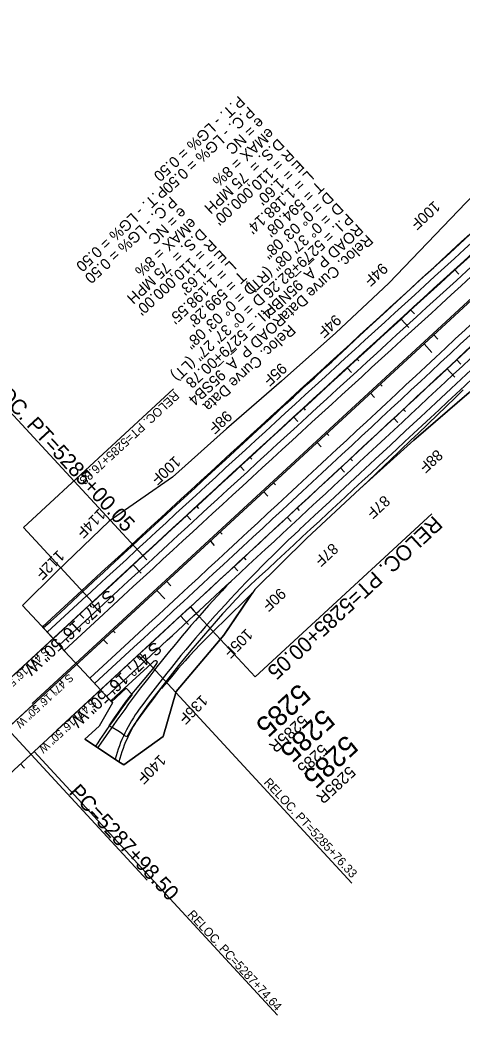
# Model space of a CAD drawing. Extents: x 2160876 to 2175990, y 601436 to 618246.
# Drawn here: x 2163718 to 2164326, y 605458 to 606830 of the extents above; entities that cross this region are included whole.
import ezdxf

# ---------------------------------------------------------------- set-up
doc = ezdxf.new("R2010")
doc.units = 0
for name, color, linetype in [('BNDY-ADJ', 7, 'Continuous'), ('BNDY-ADJ-TXT', 7, 'Continuous'), ('EX-UTIL-ELEC-TXT', 7, 'Continuous'), ('RD_DTM_Major2', 7, 'Continuous'), ('RD_EX_BldgApp_Sign', 7, 'Continuous'), ('RD_EX_BldgApp_Steps', 7, 'Continuous'), ('RD_EX_DV_TX_Prop', 7, 'Continuous'), ('RD_EX_Fence_Gate', 7, 'Continuous'), ('RD_EX_Parking_Conc', 7, 'Continuous'), ('RD_EX_RW', 7, 'Continuous'), ('RD_HC_Cl', 7, 'Continuous'), ('RD_HC_Data_Tic', 7, 'Continuous'), ('RD_HC_TX_Sta50', 7, 'Continuous'), ('RD_TX_RoadID', 7, 'Continuous')]:
    doc.layers.add(name, color=color, linetype=linetype)

msp = doc.modelspace()

# ---------------------------------------------------------------- linework, layer by layer
at = {"layer": 'BNDY-ADJ'}
msp.add_line((2172239.9, 613739.9), (2163704.8, 605858.6), dxfattribs=at)
at = {"layer": 'BNDY-ADJ-TXT'}
for p, q in [((2163817.9, 606028.4), (2163672.2, 605893.8)), ((2163883.1, 605957.8), (2163737.4, 605823.3))]:
    msp.add_line(p, q, dxfattribs=at)
for centre, radius, start, end in [((2238443, 525213.1), 110000, 132.100607, 132.719474), ((2089258, 686773.1), 110000, 312.719474, 313.338341), ((2169535, 599544.7), 8545.9, 132.71947, 164.41949)]:
    msp.add_arc(centre, radius, start, end, dxfattribs=at)
at = {"layer": 'EX-UTIL-ELEC-TXT'}
for p, q in [((2163809.8, 606037.2), (2163755.7, 605987.2)), ((2163817.9, 606028.4), (2163763.8, 605978.4)), ((2163826.1, 606019.5), (2163772, 605969.6)), ((2163874.9, 605966.6), (2163820.8, 605916.7)), ((2163883.1, 605957.8), (2163828.9, 605907.9)), ((2163891.2, 605949), (2163837.1, 605899))]:
    msp.add_line(p, q, dxfattribs=at)
for centre, radius, start, end in [((2238443, 525213.1), 110012, 132.100607, 132.719474), ((2238443, 525213.1), 110000, 132.100607, 132.719474), ((2238443, 525213.1), 109988, 132.100607, 132.719474), ((2089258, 686773.1), 109988, 312.719474, 313.338341), ((2089258, 686773.1), 110000, 312.719474, 313.338341), ((2089258, 686773.1), 110012, 312.802799, 313.338341), ((2089258, 686773.1), 110024, 312.863734, 313.338341), ((2165306.8, 604831), 1770, 132.8638, 143.5951), ((2165306.8, 604831), 1786, 136.6199, 146.0495), ((2089258, 686773.1), 110012, 312.719474, 312.802799), ((2164048.7, 605758.6), 206.9, 143.5951, 164.8838)]:
    msp.add_arc(centre, radius, start, end, dxfattribs=at)
at = {"layer": 'RD_DTM_Major2'}
for p, q in [((2164273.9, 606384), (2164284.7, 606372.3)), ((2164200.4, 606316.2), (2164205.8, 606310.3)), ((2164126.9, 606248.3), (2164132.3, 606242.5)), ((2164053.5, 606180.5), (2164058.9, 606174.6)), ((2163980, 606112.7), (2163985.4, 606106.8)), ((2163906.5, 606044.8), (2163917.4, 606033.1)), ((2163833, 605977), (2163838.5, 605971.1)), ((2163759.6, 605909.1), (2163765, 605903.3))]:
    msp.add_line(p, q, dxfattribs=at)
at = {"layer": 'RD_EX_BldgApp_Sign'}
msp.add_line((2165000.3, 607057.6), (2163734.9, 605889.1), dxfattribs=at)
at = {"layer": 'RD_EX_BldgApp_Steps'}
for p, q in [((2172672.7, 614139.6), (2163700.6, 605854.7)), ((2164255.4, 606431), (2164260.8, 606425.1)), ((2164287.3, 606396.4), (2164292.7, 606390.5)), ((2164181.6, 606363.5), (2164184.3, 606360.5)), ((2164319, 606362.1), (2164324.5, 606356.2)), ((2163648.5, 606351.1), (2163887.2, 606092.6)), ((2164213.8, 606328.6), (2164216.5, 606325.6)), ((2164107.9, 606295.9), (2164110.6, 606292.9)), ((2164245.8, 606293.9), (2164248.6, 606291)), ((2164140.3, 606260.7), (2164143, 606257.8)), ((2164034.3, 606228.2), (2164037, 606225.3)), ((2164172.6, 606225.9), (2164175.3, 606222.9)), ((2164066.9, 606192.9), (2164069.6, 606189.9)), ((2163960.7, 606160.5), (2163963.5, 606157.5)), ((2164099.3, 606157.9), (2164102, 606154.9)), ((2164284.6, 606150.3), (2164041.4, 605925.7)), ((2163993.4, 606125), (2163996.1, 606122.1)), ((2163887.2, 606092.6), (2163703.5, 605923)), ((2163887.2, 606092.7), (2163892.7, 606086.8)), ((2164025.9, 606089.9), (2164028.6, 606087)), ((2163919.9, 606057.2), (2163925.4, 606051.3)), ((2163952.4, 606022), (2163768.7, 605852.4)), ((2163813.8, 606024.8), (2163816.5, 606021.9)), ((2164041.4, 605925.7), (2163952.4, 606022)), ((2163952.5, 606022), (2163957.9, 606016.2)), ((2163846.5, 605989.4), (2163849.2, 605986.4)), ((2163740.3, 605957), (2163743, 605954)), ((2163879, 605954.2), (2163881.7, 605951.3)), ((2163773, 605921.5), (2163775.7, 605918.6)), ((2163735.2, 605886.6), (2163737.9, 605883.6)), ((2163805.5, 605886.4), (2163808.2, 605883.4)), ((2163700.6, 605854.7), (2163893, 605646.3))]:
    msp.add_line(p, q, dxfattribs=at)
for centre, start, end in [((2238512.2, 525277.4), 132.095186, 132.719474), ((2089327.4, 686837.3), 312.719474, 313.335811)]:
    msp.add_arc(centre, 110000, start, end, dxfattribs=at)
at = {"layer": 'RD_EX_Fence_Gate'}
for p, q in [((2164225.6, 606467.6), (2164152.6, 606399.2)), ((2164152.6, 606399.2), (2164077.9, 606332.8)), ((2164077.9, 606332.8), (2164002.4, 606267.1)), ((2164002.4, 606267.1), (2163927.7, 606200.7)), ((2163927.7, 606200.7), (2163841, 606140.1)), ((2163841, 606140.1), (2163768.7, 606071)), ((2163768.7, 606071), (2163721.5, 606024.2)), ((2163747.5, 605996), (2163721.5, 606024.2)), ((2163998.3, 605983.1), (2163932.8, 605905.8)), ((2163780, 605960.8), (2163812.7, 605925.5)), ((2163932.8, 605905.8), (2163915, 605844)), ((2163845.2, 605890.2), (2163826.8, 605858)), ((2163826.8, 605858), (2163807.5, 605840.2)), ((2163821.9, 605830.6), (2163807.5, 605840.2)), ((2163915, 605844), (2163860.8, 605804.7)), ((2163860.8, 605804.7), (2163854.2, 605809.1))]:
    msp.add_line(p, q, dxfattribs=at)
for points in [[(2164225.6, 606467.6), (2164332.1, 606578.3), (2164419, 606668.6), (2164457.4, 606753.8), (2164511.4, 606873.3), (2164543.9, 606914.3), (2164546.6, 606930.7)], [(2164878.1, 606761.5), (2164843.2, 606725.6), (2164806, 606692.2), (2164768.4, 606659.1), (2164729.9, 606627.2), (2164693.8, 606592.6), (2164655.6, 606560.2), (2164612.2, 606533.5), (2164562.8, 606513.4), (2164521, 606484.9), (2164446.2, 606418.5), (2164410.1, 606383.9), (2164335.8, 606317), (2164259.9, 606251.7), (2164185.8, 606184.6), (2164112.5, 606116.5), (2164041.3, 606046.2), (2163998.3, 605983.1)]]:
    msp.add_lwpolyline(points, dxfattribs=at)
at = {"layer": 'RD_EX_RW'}
for p, q in [((2164225.6, 606467.6), (2164152.6, 606399.2)), ((2164152.6, 606399.2), (2164077.9, 606332.8)), ((2164077.9, 606332.8), (2164002.4, 606267.1)), ((2164002.4, 606267.1), (2163927.7, 606200.7)), ((2163927.7, 606200.7), (2163841, 606140.1)), ((2163841, 606140.1), (2163768.7, 606071)), ((2163768.7, 606071), (2163721.5, 606024.2)), ((2163998.3, 605983.1), (2164037.6, 606040.8)), ((2164037.6, 606040.8), (2164031.7, 606035.1)), ((2163721.5, 606024.2), (2163747.5, 605996)), ((2163747.5, 605996), (2163780, 605960.8)), ((2163747.5, 605996), (2163750.2, 605993.1)), ((2163932.8, 605905.8), (2163998.3, 605983.1)), ((2163845.2, 605890.2), (2163812.7, 605925.5)), ((2163915, 605844), (2163932.8, 605905.8)), ((2163845.2, 605890.2), (2163826.8, 605858)), ((2163842.9, 605892.7), (2163845.2, 605890.2)), ((2163826.8, 605858), (2163807.5, 605840.2)), ((2163807.5, 605840.2), (2163821.9, 605830.6)), ((2163860.8, 605804.7), (2163915, 605844)), ((2163854.2, 605809.1), (2163821.9, 605830.6)), ((2163821.9, 605830.6), (2163854.2, 605809.1)), ((2163854.2, 605809.1), (2163860.8, 605804.7))]:
    msp.add_line(p, q, dxfattribs=at)
for points in [[(2164546.4, 606929.7), (2164543.9, 606914.3), (2164511.4, 606873.3), (2164457.4, 606753.8), (2164419, 606668.6), (2164332.1, 606578.3), (2164225.6, 606467.6)], [(2164185.8, 606184.6), (2164259.9, 606251.7), (2164335.8, 606317), (2164410.1, 606383.9), (2164446.2, 606418.5), (2164521, 606484.9), (2164562.8, 606513.4), (2164612.2, 606533.5), (2164655.6, 606560.2), (2164693.8, 606592.6), (2164729.9, 606627.2), (2164768.4, 606659.1), (2164806, 606692.2), (2164843.2, 606725.6), (2164878.1, 606761.5)], [(2163750.2, 605993.1), (2163759.9, 606002), (2163768.1, 606009.5), (2163780.5, 606020.9), (2163790.2, 606030.1), (2163798.6, 606037.9), (2163810.3, 606048.6), (2163819.8, 606057.4), (2163832.5, 606069.2), (2163841.4, 606077.4), (2163848.1, 606083.6), (2163861.4, 606096), (2163871, 606104.7), (2163882.2, 606115.1), (2163891.7, 606123.8), (2163909.2, 606140.1), (2163919.9, 606150), (2163938.8, 606167.4), (2163958.4, 606185.6), (2163969.7, 606196), (2163987, 606212.1), (2164000.8, 606224.6), (2164020.1, 606242.4), (2164031.4, 606252.9), (2164050.9, 606270.9), (2164063.1, 606282), (2164083, 606300.4), (2164094.4, 606310.8), (2164105.1, 606320.7), (2164112.9, 606328), (2164123.1, 606337.4), (2164137.2, 606350.5), (2164146.9, 606359.3), (2164168.5, 606379.3), (2164179.3, 606389.5), (2164197.6, 606406.4), (2164207.5, 606415.6), (2164223.2, 606430.1), (2164236.6, 606442.4), (2164255.6, 606460), (2164265.6, 606469.2), (2164275.9, 606478.8), (2164287.2, 606489.2), (2164297.4, 606498.7), (2164311.6, 606512), (2164325.4, 606524.7), (2164336.8, 606535.1)], [(2164328, 606320.6), (2164318.1, 606311.1), (2164303.3, 606296.8), (2164293.4, 606287.2), (2164278.7, 606273), (2164265.8, 606260.8), (2164256.3, 606251.9), (2164240.9, 606237.1), (2164226.3, 606223), (2164220, 606217), (2164208.7, 606206.1), (2164196.7, 606194.8), (2164185.8, 606184.6)], [(2164031.7, 606035.1), (2164021.3, 606025), (2164012, 606015.9), (2163998.3, 606002.7), (2163988.7, 605993.1), (2163977.2, 605981.9), (2163971.3, 605976), (2163966.1, 605970.6), (2163958.5, 605962.7), (2163951.2, 605954.8), (2163945.1, 605947.9), (2163935.9, 605937.3), (2163926.5, 605926), (2163914.3, 605911.5), (2163912.7, 605909.7), (2163911.8, 605909.8), (2163906.4, 605902.6), (2163901.8, 605896), (2163892.7, 605884), (2163880.1, 605867.2), (2163875.2, 605860.2), (2163870.6, 605853.1), (2163866.4, 605845.7), (2163865.3, 605843.5), (2163861.6, 605845.3), (2163861.5, 605845.3), (2163857.6, 605848.2), (2163852.5, 605851.5), (2163844.7, 605856.4), (2163844.2, 605856.7), (2163840.8, 605858.7), (2163848, 605869.5), (2163855.7, 605880.6), (2163863.2, 605890.9), (2163870.1, 605899.8), (2163876.9, 605907.9), (2163889, 605922.4), (2163900.8, 605936.6), (2163905.4, 605942.8), (2163907, 605945.3), (2163907.2, 605946), (2163907, 605946.7), (2163906.8, 605946.9), (2163906.2, 605947.5), (2163905.5, 605947.8), (2163904, 605947.9), (2163902.5, 605947.6), (2163902.2, 605947.5), (2163901.3, 605946.7), (2163893.3, 605939.3), (2163872.6, 605920), (2163849.8, 605899.1), (2163842.9, 605892.7)]]:
    msp.add_lwpolyline(points, dxfattribs=at)
at = {"layer": 'RD_HC_Cl'}
for p, q in [((2164316.2, 606485.7), (2164321.6, 606479.7)), ((2164242.4, 606418.2), (2164253.2, 606406.4)), ((2164168.6, 606350.7), (2164174, 606344.8)), ((2164305.5, 606349.9), (2164316.4, 606338.2)), ((2164094.9, 606283.2), (2164100.3, 606277.3)), ((2164232.3, 606281.7), (2164237.8, 606275.9)), ((2164021.2, 606215.6), (2164026.6, 606209.7)), ((2164159.1, 606213.6), (2164164.6, 606207.7)), ((2163947.6, 606147.9), (2163953, 606142)), ((2164085.8, 606145.5), (2164091.3, 606139.7)), ((2163874, 606080.1), (2163884.9, 606068.4)), ((2164012.5, 606077.6), (2164018, 606071.7)), ((2163800.5, 606012.3), (2163806, 606006.4)), ((2163939.1, 606009.6), (2163950, 605997.9)), ((2163727.1, 605944.5), (2163732.5, 605938.6)), ((2163865.7, 605941.8), (2163871.1, 605935.9)), ((2163792.2, 605873.9), (2163797.6, 605868.1)), ((2163718.8, 605806.1), (2163724.2, 605800.2))]:
    msp.add_line(p, q, dxfattribs=at)
at = {"layer": 'RD_HC_TX_Sta50'}
for p, q in [((2163722.9, 606131.3), (2163929.5, 606322)), ((2163722.9, 606131.3), (2163817.9, 606028.4)), ((2164174.5, 605642.2), (2163883.1, 605957.8)), ((2163737.4, 605823.3), (2164072.5, 605460.3))]:
    msp.add_line(p, q, dxfattribs=at)
at = {"layer": 'RD_TX_RoadID'}
for p, q in [((2163803, 606044.5), (2163748.9, 605994.5)), ((2163832.9, 606012.2), (2163778.7, 605962.2)), ((2163780.1, 605960.7), (2163748.9, 605994.5)), ((2163868.1, 605974), (2163814, 605924)), ((2163843.9, 605891.7), (2163814, 605924)), ((2163864, 605910.3), (2163843.9, 605891.7)), ((2163864, 605910.3), (2163872.2, 605901.5)), ((2163821.9, 605830.6), (2163854.2, 605809.1))]:
    msp.add_line(p, q, dxfattribs=at)
for centre, radius, start, end in [((2238443, 525213.1), 110022, 132.100607, 132.719474), ((2238443, 525213.1), 109978, 132.100607, 132.719474), ((2089258, 686773.1), 109978, 312.719474, 313.338341), ((2089258, 686773.1), 110034, 312.803121, 313.338341), ((2165306.8, 604831), 1764, 136.6475, 143.5951), ((2165306.8, 604831), 1790, 143.2688, 146.0495), ((2164048.7, 605758.6), 200.9, 143.5951, 165.4609)]:
    msp.add_arc(centre, radius, start, end, dxfattribs=at)

# ---------------------------------------------------------------- texts
at = {"layer": 'RD_EX_BldgApp_Steps'}
for s, height, rotation, p in [('P.T. - LG% = 0.50', 15, 222.8064, (2163912.1, 606602.4)), ('P.C. - LG% = 0.50', 15, 222.8064, (2163925.7, 606587.7)), ('e = NC', 15, 222.8064, (2163939.3, 606573)), ('eMAX = 8%', 15, 222.8064, (2163952.9, 606558.4)), ('D.S. =  75 MPH', 15, 222.8064, (2163966.5, 606543.7)), ("R = 110,000.00'", 15, 222.8064, (2163980.1, 606529)), ("E = 1.63'", 15, 222.8064, (2163993.7, 606514.3)), ("L = 1,198.55'", 15, 222.8064, (2164007.2, 606499.7)), ("T = 599.28'", 15, 222.8064, (2164020.8, 606485)), ('D = 0° 03\' 08"', 15, 222.8064, (2164034.4, 606470.3)), ('D', 15, 222.8064, (2164046.6, 606454.5)), ('    = 0° 37\' 27" (LT)', 15, 222.8064, (2164048, 606455.7)), ('P.I. = 5279+00.78', 15, 222.8064, (2164061.6, 606441)), ('ROAD P_A_95SB4', 15, 222.8064, (2164075.2, 606426.3)), ('Reloc. Curve Data', 15, 222.8064, (2164088.8, 606411.6)), ('RELOC. PT=5285+00.05', 21, 312.7195, (2163649.8, 606354.1)), ('RELOC. PT=5285+00.05', 21, 222.7195, (2164287.1, 606148.7)), ('S 47° 16\' 50" W', 17, 222.7195, (2163839.6, 606046.9)), ('S 47° 16\' 50" W', 17, 222.7195, (2163903.6, 605975.4)), ('5285', 28, 222.7195, (2164101.5, 605918.1)), ('5285', 28, 222.7195, (2164134.8, 605883.2)), ('5285', 28, 222.7195, (2164166.7, 605847.4)), ('PC=5287+98.50', 21, 312.7195, (2163784.4, 605766.3))]:
    msp.add_text(s, height=height, rotation=rotation, dxfattribs=at).set_placement(p)
at = {"layer": 'RD_EX_DV_TX_Prop'}
msp.add_text('5285', height=16, rotation=222.7195, dxfattribs=at).set_placement((2164132.9, 605834.6))
at = {"layer": 'RD_EX_Fence_Gate'}
for s, rotation, p in [('100F', 222.5234, (2164287.8, 606581.7)), ('94F', 222.5234, (2164215.7, 606496.4)), ('94F', 222.5234, (2164151.6, 606425.5)), ('95F', 222.5234, (2164076.9, 606359)), ('98F', 222.5234, (2164001.4, 606293.3)), ('88F', 222.5234, (2164291.4, 606239.7)), ('100F', 222.5234, (2163930.9, 606230.7)), ('87F', 222.5234, (2164218.8, 606176.6)), ('114F', 225.0629, (2163826.9, 606158.3)), ('112F', 225.0629, (2163770.5, 606101.1)), ('87F', 222.5234, (2164147.5, 606110.9)), ('90F', 222.5234, (2164075.5, 606049.1)), ('105F', 225.0629, (2164029.4, 605993.1)), ('136F', 225.0629, (2163967.5, 605902.2)), ('140F', 225.0629, (2163910.1, 605820))]:
    msp.add_text(s, height=15, rotation=rotation, dxfattribs=at).set_placement(p)
at = {"layer": 'RD_EX_Parking_Conc'}
msp.add_text('S 47° 16\' 50" W', height=10.8, rotation=222.7195, dxfattribs=at).set_placement((2163785.5, 605930.9))
at = {"layer": 'RD_HC_Data_Tic'}
for rotation, p in [(222.6797, (2164105.5, 605874.6)), (222.7592, (2164170.7, 605804.3))]:
    msp.add_text('5285R', height=16, rotation=rotation, dxfattribs=at).set_placement(p)
at = {"layer": 'RD_HC_TX_Sta50'}
for s, height, rotation, p in [('P.T. - LG% = 0.50', 15, 222.7195, (2164019, 606726.3)), ('P.C. - LG% = 0.50', 15, 222.7195, (2164032.5, 606711.6)), ('e = NC', 15, 222.7195, (2164046.1, 606696.9)), ('eMAX = 8%', 15, 222.7195, (2164059.7, 606682.2)), ('D.S. =  75 MPH', 15, 222.7195, (2164073.2, 606667.5)), ("R = 110,000.00'", 15, 222.7195, (2164086.8, 606652.8)), ("E = 1.60'", 15, 222.7195, (2164100.4, 606638.1)), ("L = 1,188.14'", 15, 222.7195, (2164113.9, 606623.4)), ("T = 594.08'", 15, 222.7195, (2164127.5, 606608.7)), ('D = 0° 03\' 08"', 15, 222.7195, (2164141.1, 606594)), ('D', 15, 222.7195, (2164154.6, 606579.3)), ('    = 0° 37\' 08" (RT)', 15, 222.7195, (2164154.6, 606579.3)), ('P.I. = 5279+82.26', 15, 222.7195, (2164168.2, 606564.6)), ('ROAD P_A_95NB-4', 15, 222.7195, (2164181.8, 606550)), ('Reloc. Curve Data', 15, 222.7195, (2164195.4, 606535.3)), ('RELOC. PT=5285+76.33', 12, 222.7195, (2163930.5, 606319.6)), ('S 47° 16\' 50" W', 10.8, 222.7195, (2163752.5, 605967.1)), ('S 47° 16\' 50" W', 10.8, 222.7195, (2163817.5, 605896.5)), ('RELOC. PT=5285+76.33', 12, 312.7195, (2164052.7, 605779.9)), ('RELOC. PC=5287+74.64', 12, 312.7195, (2163947.8, 605598.3))]:
    msp.add_text(s, height=height, rotation=rotation, dxfattribs=at).set_placement(p)

doc.saveas('drawing.dxf')
